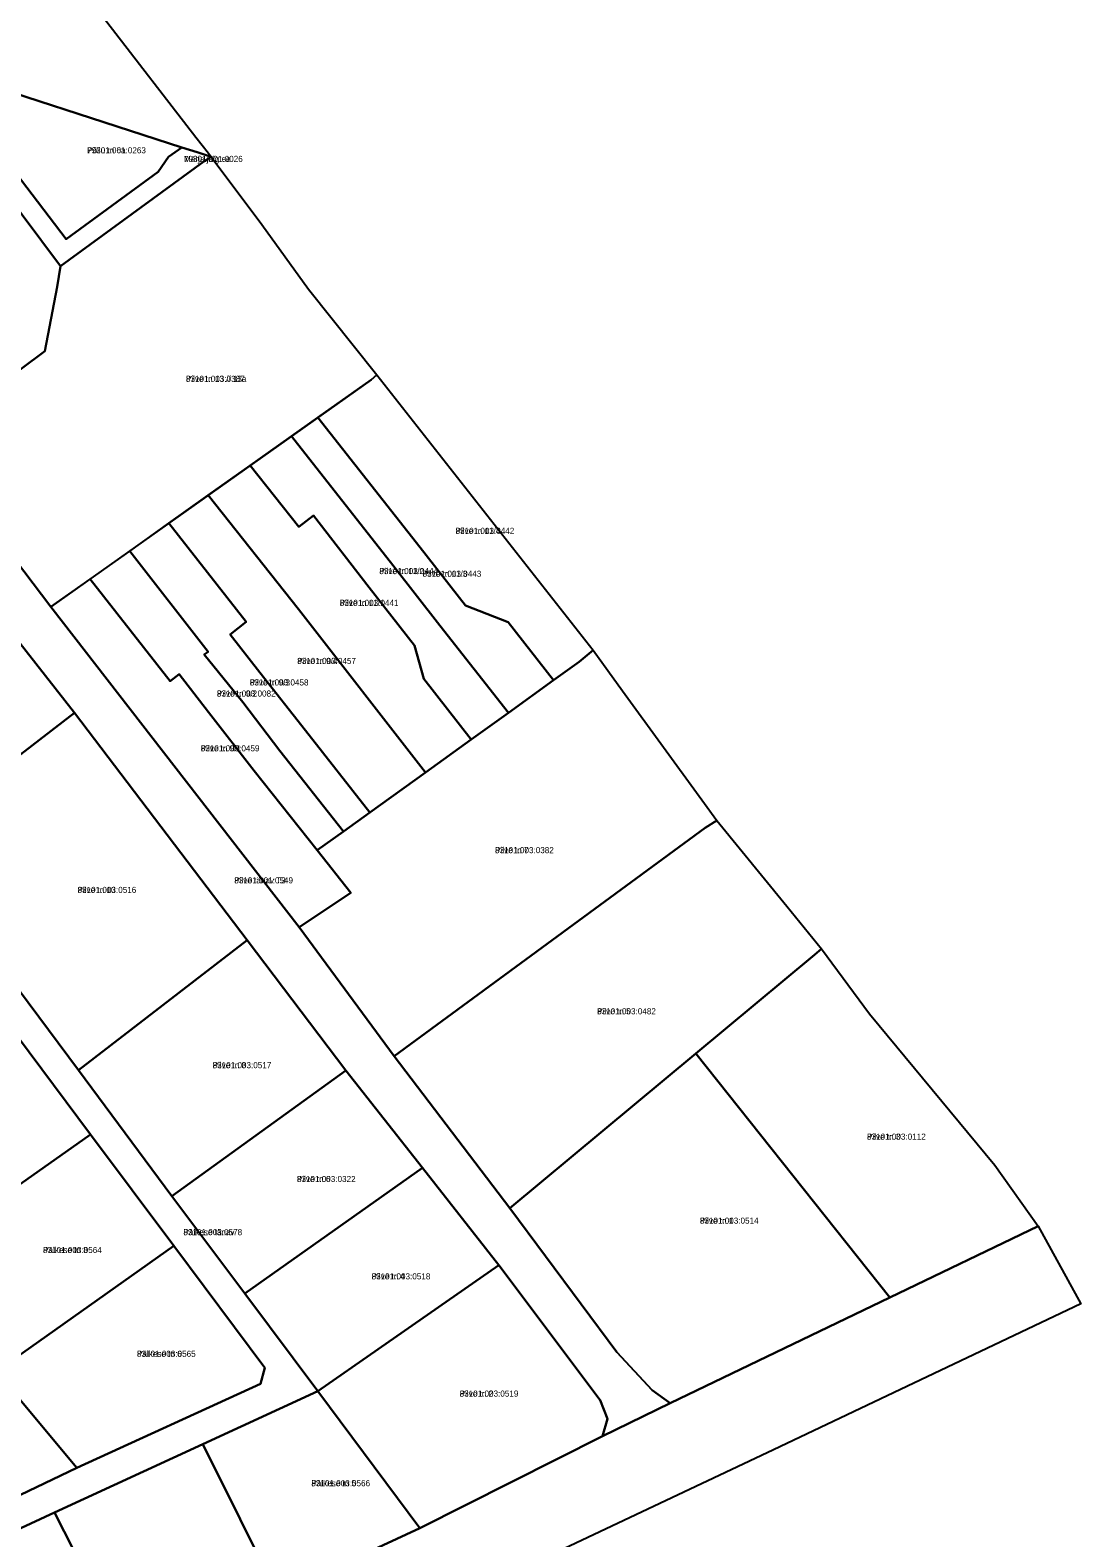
# Model space of a CAD drawing. Extents: x 643847 to 663718, y 6468443 to 6482775.
# Drawn here: x 655239.8 to 655499.2, y 6472035.4 to 6472407.5 of the extents above; entities that cross this region are included whole.
import ezdxf

# ---------------------------------------------------------------- set-up
doc = ezdxf.new("R2010")
doc.units = 0
for name, color, linetype in [('L_AADRESS', 7, 'Continuous'), ('PIIR', 7, 'Continuous'), ('TUNNUS', 7, 'Continuous')]:
    doc.layers.add(name, color=color, linetype=linetype)

msp = doc.modelspace()

# ---------------------------------------------------------------- linework, layer by layer
at = {"layer": 'PIIR'}
for points in [[(655230.08, 6472441.59), (655232.02, 6472444.04), (655236.74, 6472437.99), (655258.74, 6472409.51), (655280.75, 6472381.02), (655283.81, 6472377.06), (655284.48, 6472376.2), (655281.05, 6472377.32), (655277.26, 6472378.48), (655216.39, 6472398.2), (655209.63, 6472400.31), (655210.28, 6472407.48), (655211, 6472416.27)], [(655215.97, 6472390.95), (655208.62, 6472400.66), (655209.63, 6472400.31), (655216.39, 6472398.2), (655248.69, 6472355.9), (655271.4, 6472372.5), (655273.99, 6472376.16), (655277.26, 6472378.48), (655281.05, 6472377.32), (655284.48, 6472376.2), (655282.69, 6472375.07), (655247.29, 6472349.19), (655218.81, 6472387.19), (655195.3, 6472369.43), (655196.51, 6472374.58), (655200.26, 6472378.94)], [(655248.69, 6472355.9), (655216.39, 6472398.2), (655277.26, 6472378.48), (655273.99, 6472376.16), (655271.4, 6472372.5)], [(655187.22, 6472312.13), (655195.3, 6472369.43), (655218.81, 6472387.19), (655247.29, 6472349.19), (655246.5, 6472344.13), (655243.48, 6472328.21), (655213.86, 6472306.21)], [(655243.48, 6472328.21), (655246.5, 6472344.13), (655247.29, 6472349.19), (655282.69, 6472375.07), (655284.48, 6472376.2), (655297.02, 6472359.5), (655308.53, 6472343.5), (655325.36, 6472322.39), (655323.98, 6472321.17), (655244.92, 6472265.1), (655229.22, 6472285.8), (655222.24, 6472295.11), (655218.83, 6472299.51), (655213.86, 6472306.21)], [(655323.98, 6472321.17), (655325.36, 6472322.39), (655378.77, 6472254.4), (655375.35, 6472251.56), (655369, 6472247), (655357.78, 6472261.32), (655347.29, 6472265.48), (655336.1, 6472279.8), (655310.87, 6472311.86)], [(655310.87, 6472311.86), (655336.1, 6472279.8), (655347.29, 6472265.48), (655357.78, 6472261.32), (655369, 6472247), (655357.88, 6472239), (655340.95, 6472260.55), (655329.34, 6472275.45), (655304.36, 6472307.25)], [(655304.36, 6472307.25), (655329.34, 6472275.45), (655340.95, 6472260.55), (655357.88, 6472239), (655348.68, 6472232.37), (655337.03, 6472247.35), (655334.7, 6472255.6), (655323.53, 6472269.88), (655309.79, 6472287.64), (655306.11, 6472284.9), (655294.14, 6472299.99)], [(655294.14, 6472299.99), (655306.11, 6472284.9), (655309.79, 6472287.64), (655323.53, 6472269.88), (655334.7, 6472255.6), (655337.03, 6472247.35), (655348.68, 6472232.37), (655337.41, 6472224.26), (655306.02, 6472264.55), (655283.8, 6472292.65)], [(655283.8, 6472292.65), (655306.02, 6472264.55), (655337.41, 6472224.26), (655323.66, 6472214.36), (655307.79, 6472234.57), (655296.54, 6472248.88), (655289.19, 6472258.28), (655293.12, 6472261.41), (655274.08, 6472285.75)], [(655274.08, 6472285.75), (655293.12, 6472261.41), (655289.19, 6472258.28), (655296.54, 6472248.88), (655307.79, 6472234.57), (655323.66, 6472214.36), (655317.18, 6472209.69), (655301.49, 6472229.62), (655292.31, 6472241.6), (655282.81, 6472253.33), (655283.76, 6472254.05), (655264.4, 6472278.88)], [(655254.65, 6472271.99), (655264.4, 6472278.88), (655283.76, 6472254.05), (655282.81, 6472253.33), (655292.31, 6472241.6), (655301.49, 6472229.62), (655317.18, 6472209.69), (655310.65, 6472205.04), (655295.12, 6472224.69), (655283.85, 6472239.1), (655276.6, 6472248.5), (655274.35, 6472246.74)], [(655254.65, 6472271.99), (655274.35, 6472246.74), (655276.6, 6472248.5), (655283.85, 6472239.1), (655295.12, 6472224.69), (655310.65, 6472205.04), (655318.94, 6472194.54), (655306.19, 6472186.03), (655244.92, 6472265.1)], [(655231.63, 6472263.3), (655250.77, 6472238.98), (655209.59, 6472207.28), (655191.04, 6472232.25)], [(655378.77, 6472254.4), (655386.02, 6472244.43), (655405.62, 6472217.48), (655409.33, 6472212.39), (655406.45, 6472210.56), (655329.68, 6472154.26), (655306.19, 6472186.03), (655318.94, 6472194.54), (655310.65, 6472205.04), (655317.18, 6472209.69), (655323.66, 6472214.36), (655337.41, 6472224.26), (655348.68, 6472232.37), (655357.88, 6472239), (655369, 6472247), (655375.35, 6472251.56)], [(655250.77, 6472238.98), (655293.42, 6472182.83), (655251.72, 6472150.74), (655209.59, 6472207.28)], [(655406.45, 6472210.56), (655409.33, 6472212.39), (655426.6, 6472191.22), (655435.19, 6472180.69), (655433.42, 6472179.21), (655404.17, 6472154.88), (655358.24, 6472116.74), (655329.68, 6472154.26)], [(655293.42, 6472182.83), (655317.74, 6472150.72), (655274.77, 6472119.69), (655251.72, 6472150.74)], [(655254.74, 6472134.91), (655209.34, 6472102.92), (655194.1, 6472121.06), (655174.92, 6472144.25), (655221.44, 6472179.4)], [(655404.17, 6472154.88), (655433.42, 6472179.21), (655435.19, 6472180.69), (655447, 6472164.68), (655477.9, 6472127.31), (655488.61, 6472112.27), (655452.02, 6472094.64)], [(655384.62, 6472081.15), (655358.24, 6472116.74), (655404.17, 6472154.88), (655452.02, 6472094.64), (655397.83, 6472068.61), (655393.37, 6472071.79)], [(655317.74, 6472150.72), (655336.69, 6472126.69), (655292.8, 6472095.63), (655274.77, 6472119.69)], [(655275.29, 6472107.4), (655231.45, 6472076.37), (655213.29, 6472098.11), (655209.34, 6472102.92), (655254.74, 6472134.91)], [(655336.69, 6472126.69), (655355.54, 6472102.67), (655310.83, 6472071.59), (655292.8, 6472095.63)], [(655297.78, 6472077.3), (655296.69, 6472073.35), (655251.34, 6472052.66), (655231.45, 6472076.37), (655275.29, 6472107.4)], [(655355.54, 6472102.67), (655380.49, 6472069.32), (655382.35, 6472064.7), (655381.12, 6472060.46), (655335.99, 6472037.75), (655310.83, 6472071.59)], [(655231.45, 6472076.37), (655251.34, 6472052.66), (655225.34, 6472040.19), (655192.92, 6472082.62), (655213.29, 6472098.11)], [(655335.99, 6472037.75), (655300.85, 6472021.44), (655282.47, 6472058.51), (655310.83, 6472071.59)], [(655300.85, 6472021.44), (655264.75, 6472004.41), (655245.83, 6472041.59), (655282.47, 6472058.51)], [(655228.82, 6471992.75), (655203.82, 6472022.1), (655245.83, 6472041.59), (655264.75, 6472004.41), (655245.2, 6471995.17), (655239.85, 6471993.76)]]:
    msp.add_lwpolyline(points, close=True, dxfattribs=at)
for points in [[(655229.22, 6472285.8), (655244.92, 6472265.1), (655306.19, 6472186.03), (655329.68, 6472154.26), (655358.24, 6472116.74), (655384.63, 6472081.15), (655393.37, 6472071.79), (655397.83, 6472068.61), (655381.12, 6472060.46), (655382.35, 6472064.7), (655380.49, 6472069.32), (655355.54, 6472102.67), (655336.69, 6472126.69), (655317.74, 6472150.72), (655293.42, 6472182.83), (655250.77, 6472238.98), (655231.63, 6472263.3)], [(655209.59, 6472207.28), (655251.72, 6472150.74), (655274.77, 6472119.69), (655292.8, 6472095.63), (655310.83, 6472071.59), (655282.47, 6472058.51), (655245.83, 6472041.59), (655203.82, 6472022.1)], [(655225.34, 6472040.19), (655251.34, 6472052.66), (655296.69, 6472073.35), (655297.78, 6472077.3), (655275.29, 6472107.4), (655254.74, 6472134.91), (655221.44, 6472179.4)], [(655300.85, 6472021.44), (655335.99, 6472037.75), (655381.12, 6472060.46), (655397.83, 6472068.61), (655452.02, 6472094.64), (655488.61, 6472112.27), (655499.17, 6472093.13), (655423.3, 6472057.08), (655321.35, 6472008.92)]]:
    msp.add_lwpolyline(points, dxfattribs=at)

# ---------------------------------------------------------------- texts
at = {"layer": 'L_AADRESS'}
for s, p in [('Põllu tn 6a', (655253.89, 6472377.05)), ('Märja jalgtee', (655277.8, 6472374.93)), ('Pilve tn 13 // 13a', (655278.27, 6472320.65)), ('Pilve tn 11/4', (655344.82, 6472283.13)), ('Pilve tn 11/2', (655326.01, 6472273.2)), ('Pilve tn 11/3', (655336.68, 6472272.54)), ('Pilve tn 11/1', (655316.24, 6472265.37)), ('Pilve tn 9/4', (655305.74, 6472251.03)), ('Pilve tn 9/3', (655294.03, 6472245.72)), ('Pilve tn 9/2', (655285.91, 6472242.98)), ('Pilve tn 9/1', (655281.93, 6472229.46)), ('Pilve tn 7', (655354.58, 6472204.33)), ('Pilve tänav T3', (655290.2, 6472196.87)), ('Pilve tn 10', (655251.51, 6472194.52)), ('Pilve tn 5', (655379.77, 6472164.57)), ('Pilve tn 8', (655284.86, 6472151.26)), ('Pilve tn 3', (655446.39, 6472133.62)), ('Pilve tn 6', (655305.66, 6472123.17)), ('Pilve tn 1', (655405.13, 6472112.89)), ('Päikese tänav', (655277.65, 6472110.05)), ('Päikese tn 8', (655243, 6472105.64)), ('Pilve tn 4', (655324.11, 6472099.14)), ('Päikese tn 6', (655266.18, 6472080.03)), ('Pilve tn 2', (655345.84, 6472070.21)), ('Päikese tn 5', (655309.23, 6472048.09))]:
    msp.add_text(s, height=1.5, dxfattribs=at).set_placement(p)
at = {"layer": 'TUNNUS'}
for s, p in [('79301:001:0263', (655253.89, 6472377.05)), ('79301:001:0026', (655277.8, 6472374.93)), ('83101:003:0387', (655278.27, 6472320.65)), ('83101:003:0442', (655344.82, 6472283.13)), ('83101:003:0444', (655326.01, 6472273.2)), ('83101:003:0443', (655336.68, 6472272.54)), ('83101:003:0441', (655316.24, 6472265.37)), ('83101:003:0457', (655305.74, 6472251.03)), ('83101:003:0458', (655294.03, 6472245.72)), ('83101:003:0082', (655285.91, 6472242.98)), ('83101:003:0459', (655281.93, 6472229.46)), ('83101:003:0382', (655354.58, 6472204.33)), ('83101:001:0549', (655290.2, 6472196.87)), ('83101:003:0516', (655251.51, 6472194.52)), ('83101:003:0482', (655379.77, 6472164.57)), ('83101:003:0517', (655284.86, 6472151.26)), ('83101:003:0112', (655446.39, 6472133.62)), ('83101:003:0322', (655305.66, 6472123.17)), ('83101:003:0514', (655405.13, 6472112.89)), ('83101:003:0578', (655277.65, 6472110.05)), ('83101:003:0564', (655243, 6472105.64)), ('83101:003:0518', (655324.11, 6472099.14)), ('83101:003:0565', (655266.18, 6472080.03)), ('83101:003:0519', (655345.84, 6472070.21)), ('83101:003:0566', (655309.23, 6472048.09))]:
    msp.add_text(s, height=1.5, dxfattribs=at).set_placement(p)

doc.saveas('drawing.dxf')
